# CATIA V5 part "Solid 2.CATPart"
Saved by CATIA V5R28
Part number: Part6.1
Bounding box of the stored display mesh (mm): x -75 to 75.038, y 0 to 600, z -20 to 20
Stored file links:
  H:\Maskiningenjör\Examensarbete\Klart\Klart & Skickas\Solid 2.CATPart
  H:\Examensarbete\Catia filer\Klar assembly\Klara blad av SOLID med hal\BladDesign.CATPart
  H:\Examensarbete\FullAssembly_KlartMedStativ\Assembly_Fullt+Stativ.CATProduct
  H:\Maskiningenjör\Examensarbete\Klart\Klart & Skickas\HJALPMEDEL.CATPart
  H:\Maskiningenjör\Examensarbete\Klart\Stativ o allt\AssemblyBlad_OriginalDesign.CATProduct
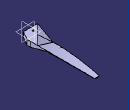
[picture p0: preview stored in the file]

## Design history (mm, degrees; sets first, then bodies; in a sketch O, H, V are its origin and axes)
Set1
  DatumPoint1: linked copy from another document
  DatumPoint2: linked copy from another document
Body1 (main body)
Body2 "Solid Blad"
  Solid1: solid without history
  Sketch1, origin (-8.6759, 32.5518, 20), H (1, 0, 0), V (0, 1, 0), geometry linked from another document
  Hole1: placed by Sketch1, at (-8.3732, 32.0268, 20) direction (0, 0, -1), diameter 12, through (limit type 3)
  Sketch2 "Positioning sketch - Assembly Hole.3" on face of Solid1, origin (-8.6759, 32.5518, 20), H (1, 0, 0), V (0, 1, 0)
    point P1 (0.3027, -0.525)
    reference projected point E1 (0.3027, -0.525) from vertex of DatumPoint2
    coincidence: E1 P1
